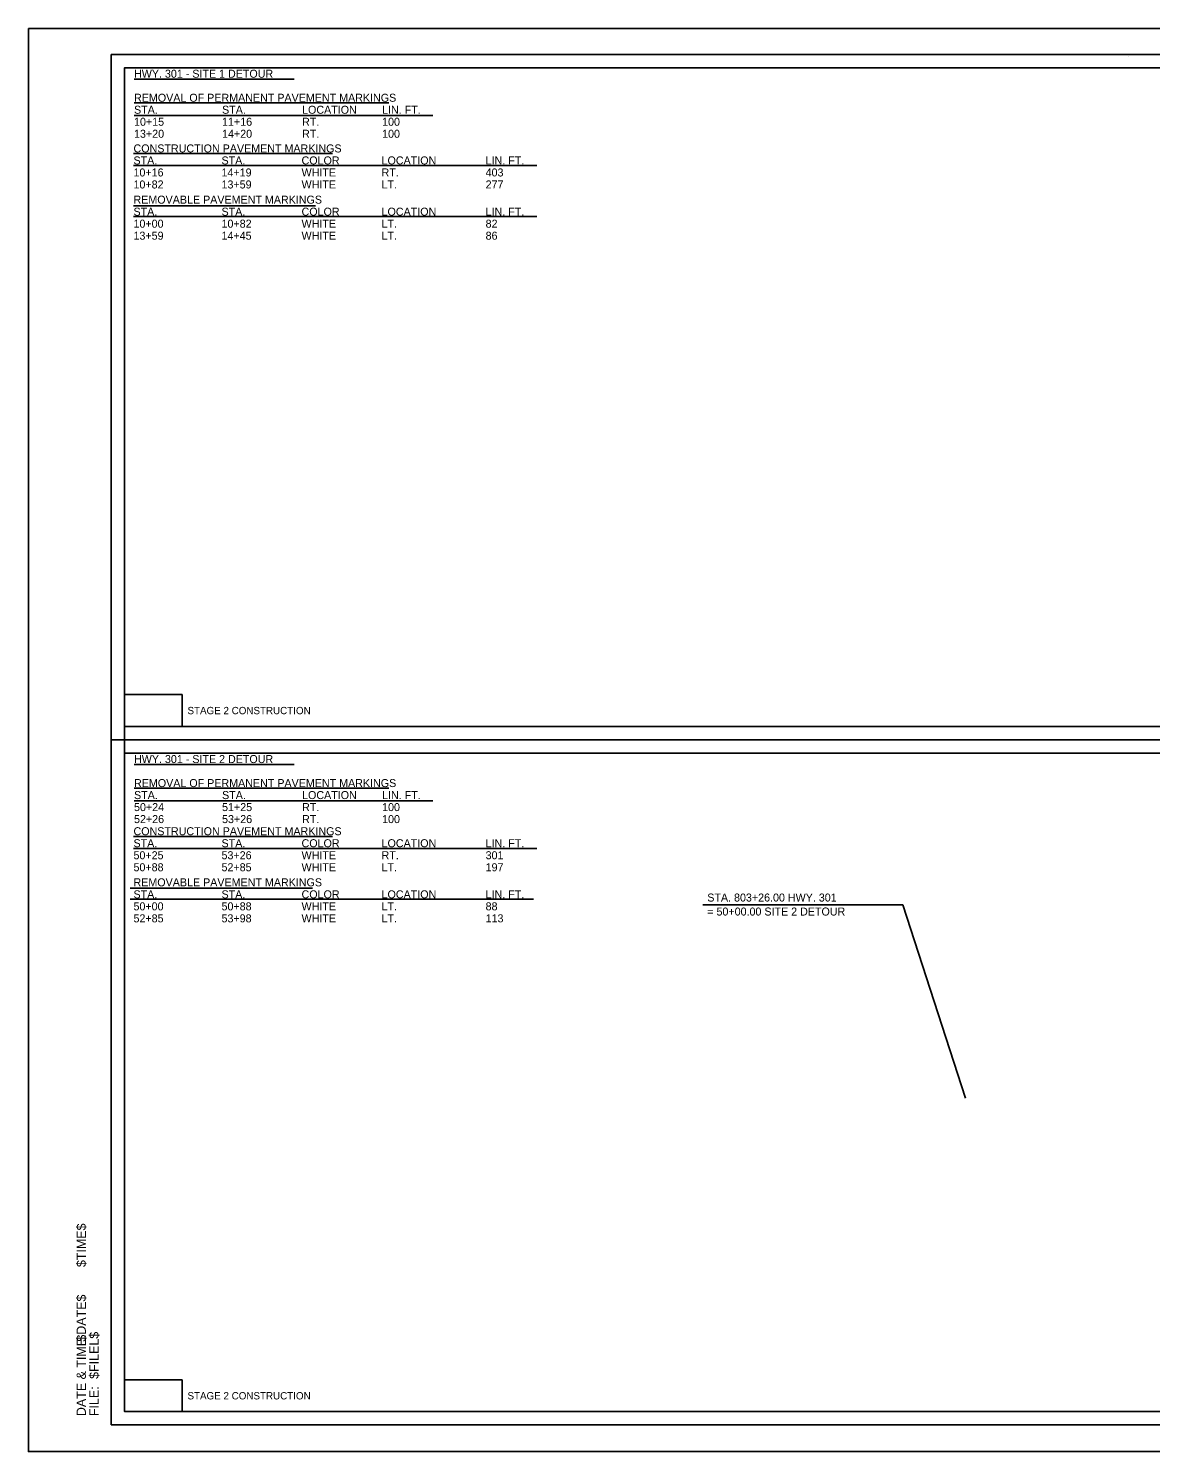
# Model space of a CAD drawing. Extents: x 1368648 to 1927880, y -1037443 to 380209.
# Drawn here: x 1375810 to 1376651, y 378686 to 379753 of the extents above; entities that cross this region are included whole.
import ezdxf

# ---------------------------------------------------------------- set-up
doc = ezdxf.new("R2010")
doc.units = 0
for name, color, linetype in [('Default', 7, 'Continuous'), ('R_Border', 7, 'Continuous'), ('R_Border Notes', 7, 'Continuous'), ('R_Detour Annot Limits', 7, 'Continuous'), ('R_No Plot', 7, 'Continuous')]:
    doc.layers.add(name, color=color, linetype=linetype)

msp = doc.modelspace()

# ---------------------------------------------------------------- linework, layer by layer
at = {"layer": 'Default'}
for p, q in [((1375889.3, 379714.7), (1376009.3, 379714.7)), ((1375889.3, 379696.9), (1376080.3, 379696.9)), ((1375889.3, 379687.5), (1376113.3, 379687.5)), ((1375889, 379658.9), (1376038, 379658.9)), ((1375889, 379649.9), (1376191.2, 379649.9)), ((1375889, 379619.9), (1376025.4, 379619.9)), ((1375889, 379611.7), (1376191.2, 379611.7)), ((1375889.3, 379201), (1376009.3, 379201)), ((1375889.3, 379183.2), (1376080.3, 379183.2)), ((1375889.3, 379173.9), (1376113.3, 379173.9)), ((1375889, 379147.1), (1376038, 379147.1)), ((1375889, 379138.1), (1376191.2, 379138.1)), ((1375886.5, 379108.3), (1376023, 379108.3)), ((1375886.5, 379100), (1376188.8, 379100))]:
    msp.add_line(p, q, dxfattribs=at)
for points in [[(1375882.2, 379229.6), (1375925.3, 379229.6), (1375925.3, 379253.4), (1375882.2, 379253.4), (1375882.2, 379229.6)], [(1375882.2, 378716), (1375925.3, 378716), (1375925.3, 378739.7), (1375882.2, 378739.7), (1375882.2, 378716)]]:
    msp.add_lwpolyline(points, dxfattribs=at)
at = {"layer": 'R_Border'}
for p, q in [((1375872.2, 379733.3), (1377453.1, 379733.3)), ((1375872.2, 378706), (1375872.2, 379733.3)), ((1376634.8, 379732), (1376634.8, 379732)), ((1376634.8, 379732), (1376634.8, 379732)), ((1377453.1, 379219.6), (1375872.2, 379219.6)), ((1375872.2, 378706), (1375872.2, 378706)), ((1377453.1, 378706), (1375872.2, 378706))]:
    msp.add_line(p, q, dxfattribs=at)
at = {"layer": 'R_Detour Annot Limits'}
msp.add_lwpolyline([(1376315.7, 379095.8), (1376465.7, 379095.8), (1376512.7, 378950.9)], dxfattribs=at)
at = {"layer": 'R_No Plot'}
for points in [[(1375810.1, 379752.7), (1377476.8, 379752.7), (1377476.8, 378686), (1375810.1, 378686)], [(1377443.1, 379229.6), (1375882.2, 379229.6), (1375882.2, 379723.3), (1377129.9, 379723.3), (1377129.9, 379673.9), (1377217.6, 379673.9), (1377338.1, 379673.9), (1377338.1, 379562.2), (1377443.1, 379562.2)], [(1377443.1, 379229.6), (1375882.2, 379229.6), (1375882.2, 379723.3), (1377129.9, 379723.3), (1377129.9, 379673.9), (1377217.6, 379673.9), (1377338.1, 379673.9), (1377338.1, 379562.2), (1377443.1, 379562.2)], [(1377443.1, 379229.6), (1375882.2, 379229.6), (1375882.2, 379723.3), (1377129.9, 379723.3), (1377129.9, 379673.9), (1377217.6, 379673.9), (1377338.1, 379673.9), (1377338.1, 379562.2), (1377443.1, 379562.2)], [(1377443.1, 379229.6), (1375882.2, 379229.6), (1375882.2, 379723.3), (1377129.9, 379723.3), (1377129.9, 379673.9), (1377217.6, 379673.9), (1377338.1, 379673.9), (1377338.1, 379562.2), (1377443.1, 379562.2)], [(1377443.1, 379229.6), (1375882.2, 379229.6), (1375882.2, 379723.3), (1377129.9, 379723.3), (1377129.9, 379673.9), (1377217.6, 379673.9), (1377338.1, 379673.9), (1377338.1, 379562.2), (1377443.1, 379562.2)], [(1377443.1, 379229.6), (1375882.2, 379229.6), (1375882.2, 379723.3), (1377129.9, 379723.3), (1377129.9, 379673.9), (1377217.6, 379673.9), (1377338.1, 379673.9), (1377338.1, 379562.2), (1377443.1, 379562.2)], [(1377443.1, 379229.6), (1375882.2, 379229.6), (1375882.2, 379723.3), (1377129.9, 379723.3), (1377129.9, 379673.9), (1377217.6, 379673.9), (1377338.1, 379673.9), (1377338.1, 379562.2), (1377443.1, 379562.2)], [(1375882.2, 379723.3), (1377129.9, 379723.3), (1377129.9, 379673.9), (1377217.6, 379673.9), (1377338.1, 379673.9), (1377338.1, 379562.2), (1377443.1, 379562.2), (1377443.1, 378716), (1375882.2, 378716)], [(1375882.2, 379209.6), (1377443.1, 379209.6), (1377443.1, 378716), (1375882.2, 378716)], [(1375882.2, 379209.6), (1377443.1, 379209.6), (1377443.1, 378716), (1375882.2, 378716)], [(1375882.2, 379209.6), (1377443.1, 379209.6), (1377443.1, 378716), (1375882.2, 378716)], [(1375882.2, 379209.6), (1377443.1, 379209.6), (1377443.1, 378716), (1375882.2, 378716)], [(1375882.2, 379209.6), (1377443.1, 379209.6), (1377443.1, 378716), (1375882.2, 378716)], [(1375882.2, 379209.6), (1377443.1, 379209.6), (1377443.1, 378716), (1375882.2, 378716)], [(1375882.2, 379209.6), (1377443.1, 379209.6), (1377443.1, 378716), (1375882.2, 378716)]]:
    msp.add_lwpolyline(points, close=True, dxfattribs=at)

# ---------------------------------------------------------------- texts
at = {"layer": 'Default'}
for s, height, p in [('HWY. 301 - SITE 1 DETOUR', 6, (1375889.3, 379715.8)), ('REMOVAL OF PERMANENT PAVEMENT MARKINGS', 6, (1375889.3, 379697.8)), ('STA.', 6, (1375889.3, 379688.8)), ('STA.', 6, (1375955.3, 379688.8)), ('LOCATION', 6, (1376015.3, 379688.8)), ('LIN. FT.', 6, (1376075.3, 379688.8)), ('10+15 ', 6, (1375889.3, 379679.8)), ('11+16', 6, (1375955.3, 379679.8)), ('RT.', 6, (1376015.3, 379679.8)), ('100', 6, (1376075.3, 379679.8)), ('13+20', 6, (1375889.3, 379670.8)), ('14+20', 6, (1375955.3, 379670.8)), ('RT.', 6, (1376015.3, 379670.8)), ('100', 6, (1376075.3, 379670.8)), ('CONSTRUCTION PAVEMENT MARKINGS', 6, (1375888.9, 379659.8)), ('STA.', 6, (1375888.9, 379650.8)), ('STA.', 6, (1375954.9, 379650.8)), ('COLOR', 6, (1376014.9, 379650.8)), ('LOCATION', 6, (1376074.9, 379650.8)), ('LIN. FT.', 6, (1376152.9, 379650.8)), ('10+16', 6, (1375888.9, 379641.8)), ('14+19', 6, (1375954.9, 379641.8)), ('WHITE', 6, (1376014.9, 379641.8)), ('RT.', 6, (1376074.9, 379641.8)), ('403', 6, (1376152.9, 379641.8)), ('10+82', 6, (1375888.9, 379632.8)), ('13+59', 6, (1375954.9, 379632.8)), ('WHITE', 6, (1376014.9, 379632.8)), ('LT.', 6, (1376074.9, 379632.8)), ('277', 6, (1376152.9, 379632.8)), ('REMOVABLE PAVEMENT MARKINGS', 6, (1375888.9, 379621.4)), ('STA.', 6, (1375888.9, 379612.4)), ('STA.', 6, (1375954.9, 379612.4)), ('COLOR', 6, (1376014.9, 379612.4)), ('LOCATION', 6, (1376074.9, 379612.4)), ('LIN. FT.', 6, (1376152.9, 379612.4)), ('10+00', 6, (1375888.9, 379603.4)), ('10+82', 6, (1375954.9, 379603.4)), ('WHITE', 6, (1376014.9, 379603.4)), ('LT.', 6, (1376074.9, 379603.4)), ('82', 6, (1376152.9, 379603.4)), ('13+59', 6, (1375888.9, 379594.4)), ('14+45', 6, (1375954.9, 379594.4)), ('WHITE', 6, (1376014.9, 379594.4)), ('LT.', 6, (1376074.9, 379594.4)), ('86', 6, (1376152.9, 379594.4)), ('  STAGE 2 CONSTRUCTION', 5.5, (1375925.3, 379238.7)), ('HWY. 301 - SITE 2 DETOUR', 6, (1375889.3, 379202.1)), ('REMOVAL OF PERMANENT PAVEMENT MARKINGS', 6, (1375889.3, 379184.1)), ('STA.', 6, (1375889.3, 379175.1)), ('STA.', 6, (1375955.3, 379175.1)), ('LOCATION', 6, (1376015.3, 379175.1)), ('LIN. FT.', 6, (1376075.3, 379175.1)), ('50+24 ', 6, (1375889.3, 379166.1)), ('51+25', 6, (1375955.3, 379166.1)), ('RT.', 6, (1376015.3, 379166.1)), ('100', 6, (1376075.3, 379166.1)), ('52+26', 6, (1375889.3, 379157.1)), ('53+26', 6, (1375955.3, 379157.1)), ('RT.', 6, (1376015.3, 379157.1)), ('100', 6, (1376075.3, 379157.1)), ('CONSTRUCTION PAVEMENT MARKINGS', 6, (1375888.9, 379148)), ('STA.', 6, (1375888.9, 379139)), ('STA.', 6, (1375954.9, 379139)), ('COLOR', 6, (1376014.9, 379139)), ('LOCATION', 6, (1376074.9, 379139)), ('LIN. FT.', 6, (1376152.9, 379139)), ('50+25', 6, (1375888.9, 379130)), ('53+26', 6, (1375954.9, 379130)), ('WHITE', 6, (1376014.9, 379130)), ('RT.', 6, (1376074.9, 379130)), ('301', 6, (1376152.9, 379130)), ('50+88', 6, (1375888.9, 379121)), ('52+85', 6, (1375954.9, 379121)), ('WHITE', 6, (1376014.9, 379121)), ('LT.', 6, (1376074.9, 379121)), ('197', 6, (1376152.9, 379121)), ('REMOVABLE PAVEMENT MARKINGS', 6, (1375888.9, 379109.7)), ('STA.', 6, (1375888.9, 379100.7)), ('STA.', 6, (1375954.9, 379100.7)), ('COLOR', 6, (1376014.9, 379100.7)), ('LOCATION', 6, (1376074.9, 379100.7)), ('LIN. FT.', 6, (1376152.9, 379100.7)), ('50+00', 6, (1375888.9, 379091.7)), ('50+88', 6, (1375954.9, 379091.7)), ('WHITE', 6, (1376014.9, 379091.7)), ('LT.', 6, (1376074.9, 379091.7)), ('88', 6, (1376152.9, 379091.7)), ('52+85', 6, (1375888.9, 379082.7)), ('53+98', 6, (1375954.9, 379082.7)), ('WHITE', 6, (1376014.9, 379082.7)), ('LT.', 6, (1376074.9, 379082.7)), ('113', 6, (1376152.9, 379082.7)), ('  STAGE 2 CONSTRUCTION', 5.5, (1375925.3, 378725.1))]:
    msp.add_text(s, height=height, dxfattribs=at).set_placement(p)
at = {"layer": 'R_Border Notes'}
for s, height, p in [('$TIME$', 6.98, (1375853.2, 378824.3)), ('$DATE$', 6.98, (1375853.2, 378768.4)), ('DATE & TIME:', 6.984, (1375853.2, 378712.6)), ('$FILEL$', 6.98, (1375862.8, 378740.5)), ('FILE: ', 6.98, (1375862.8, 378712.6))]:
    msp.add_text(s, height=height, rotation=90, dxfattribs=at).set_placement(p)
at = {"layer": 'R_Detour Annot Limits'}
for s, p in [('STA. 803+26.00 HWY. 301', (1376319.1, 379098.3)), ('= 50+00.00 SITE 2 DETOUR', (1376319.1, 379087.8))]:
    msp.add_text(s, height=6, rotation=0.0001, dxfattribs=at).set_placement(p)

doc.saveas('drawing.dxf')
